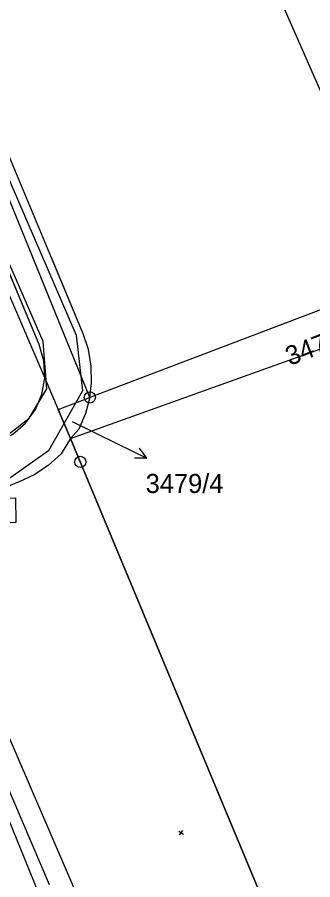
# Model space of a CAD drawing. Extents: x -834064 to -833847, y -1109181 to -1108930.
# Drawn here: x -833930.2 to -833903.8, y -1109136 to -1109058.9 of the extents above; entities that cross this region are included whole.
import ezdxf

# ---------------------------------------------------------------- set-up
doc = ezdxf.new("R2010")
doc.units = 0
for name, color, linetype in [('Hranice parcel', 7, 'Continuous'), ('Parcelní čísla', 7, 'Continuous'), ('Pop  PČ popisy', 7, 'Continuous'), ('Vrstva 49', 7, 'Continuous'), ('Vrstva 51', 7, 'Continuous'), ('Vrstva 53', 7, 'Continuous'), ('Značky bodu BP', 7, 'Continuous')]:
    doc.layers.add(name, color=color, linetype=linetype)

msp = doc.modelspace()

# ---------------------------------------------------------------- linework, layer by layer
at = {"layer": 'Hranice parcel'}
for p, q in [((-833895.8, -1109082.28), (-833914.822, -1109038.767)), ((-833923.74, -1109092.89), (-833941.325, -1109049.812)), ((-833923.74, -1109092.89), (-833928.835, -1109080.41)), ((-833895.8, -1109082.28), (-833923.74, -1109092.89)), ((-833895.8, -1109082.28), (-833923.74, -1109092.89)), ((-833925.47, -1109096.55), (-833894.43, -1109085.46)), ((-833925.47, -1109096.55), (-833894.43, -1109085.46)), ((-833927.77, -1109091.16), (-833926.57, -1109093.96)), ((-833927.77, -1109091.16), (-833926.57, -1109093.96)), ((-833926.57, -1109093.96), (-833923.74, -1109092.89)), ((-833926.57, -1109093.96), (-833923.74, -1109092.89)), ((-833925.47, -1109096.55), (-833926.57, -1109093.96)), ((-833925.47, -1109096.55), (-833926.57, -1109093.96))]:
    msp.add_line(p, q, dxfattribs=at)
for points in [[(-833923.74, -1109092.89), (-833923.58, -1109091.6), (-833923.62, -1109090.1), (-833923.87, -1109088.62), (-833924.35, -1109087.2), (-833940.145, -1109049.32)], [(-833944.996, -1109051.342), (-833931.74, -1109081.87), (-833927.77, -1109091.16)], [(-833927.77, -1109091.16), (-833927.85, -1109089.61), (-833928.27, -1109088.17), (-833943.833, -1109050.857)], [(-833932.374, -1109080.41), (-833931.74, -1109081.87), (-833927.77, -1109091.16)], [(-833927.77, -1109091.16), (-833927.85, -1109089.61), (-833928.27, -1109088.17), (-833931.507, -1109080.41)], [(-833923.74, -1109092.89), (-833923.58, -1109091.6), (-833923.62, -1109090.1), (-833923.87, -1109088.62), (-833924.35, -1109087.2), (-833927.181, -1109080.41)], [(-833951.04, -1109104.84), (-833931.81, -1109096.82), (-833930.62, -1109096.17), (-833929.48, -1109095.19), (-833928.61, -1109093.97), (-833928.02, -1109092.59), (-833927.77, -1109091.16)], [(-833951.04, -1109104.84), (-833931.81, -1109096.82), (-833930.62, -1109096.17), (-833929.48, -1109095.19), (-833928.61, -1109093.97), (-833928.02, -1109092.59), (-833927.77, -1109091.16)], [(-833923.74, -1109092.89), (-833924.13, -1109094.33), (-833924.72, -1109095.71), (-833925.47, -1109096.55)], [(-833923.74, -1109092.89), (-833924.13, -1109094.33), (-833924.72, -1109095.71), (-833925.47, -1109096.55)], [(-833925.47, -1109096.55), (-833926.31, -1109097.93), (-833927.42, -1109098.94), (-833928.67, -1109099.77), (-833929.72, -1109100.28), (-833932.81, -1109101.57), (-833932.34, -1109101.88), (-833930.39, -1109101.86), (-833930.36, -1109104.07), (-833939.02, -1109104.16), (-833949.57, -1109108.56)], [(-833925.47, -1109096.55), (-833926.31, -1109097.93), (-833927.42, -1109098.94), (-833928.67, -1109099.77), (-833929.72, -1109100.28), (-833932.81, -1109101.57), (-833932.34, -1109101.88), (-833930.39, -1109101.86), (-833930.36, -1109104.07), (-833939.02, -1109104.16), (-833949.57, -1109108.56)], [(-833905.178, -1109148.501), (-833906.97, -1109140.92), (-833924.59, -1109098.65), (-833925.47, -1109096.55)], [(-833905.178, -1109148.501), (-833906.97, -1109140.92), (-833924.59, -1109098.65), (-833925.47, -1109096.55)]]:
    msp.add_lwpolyline(points, dxfattribs=at)
at = {"layer": 'Pop  PČ popisy'}
for p, q in [((-833925.31, -1109095.03), (-833921.33, -1109096.99)), ((-833925.31, -1109095.03), (-833921.33, -1109096.99)), ((-833921.33, -1109096.99), (-833918.633, -1109098.306)), ((-833921.33, -1109096.99), (-833918.633, -1109098.306)), ((-833918.633, -1109098.306), (-833919.313, -1109097.416)), ((-833918.633, -1109098.306), (-833919.313, -1109097.416)), ((-833918.633, -1109098.306), (-833919.752, -1109098.317)), ((-833918.633, -1109098.306), (-833919.752, -1109098.317))]:
    msp.add_line(p, q, dxfattribs=at)
at = {"layer": 'Vrstva 49'}
for p, q in [((-833915.723, -1109131.959), (-833915.433, -1109131.551)), ((-833915.782, -1109131.61), (-833915.374, -1109131.9))]:
    msp.add_line(p, q, dxfattribs=at)
for points in [[(-833928.364, -1109137.035), (-833940.743, -1109106.659)], [(-833927.334, -1109136.417), (-833939.456, -1109108.148), (-833938.208, -1109106.483)], [(-833938.208, -1109106.483), (-833925.197, -1109136.624), (-833917.678, -1109153.71)]]:
    msp.add_lwpolyline(points, dxfattribs=at)
at = {"layer": 'Vrstva 51'}
for points in [[(-833940.892, -1109049.632), (-833933.81, -1109066.914), (-833924.957, -1109087.341), (-833924.384, -1109092.301), (-833927.433, -1109097.655), (-833931.105, -1109100.236)], [(-833932.56, -1109097.362), (-833929.169, -1109094.739), (-833927.592, -1109092.134), (-833927.925, -1109087.909), (-833936.504, -1109068.244), (-833943.634, -1109050.774)]]:
    msp.add_lwpolyline(points, dxfattribs=at)
at = {"layer": 'Vrstva 53'}
for points in [[(-833944.996, -1109051.342), (-833931.74, -1109081.87), (-833927.77, -1109091.16)], [(-833927.77, -1109091.16), (-833926.57, -1109093.96), (-833925.47, -1109096.55), (-833924.59, -1109098.65), (-833906.97, -1109140.92), (-833905.178, -1109148.501)]]:
    msp.add_lwpolyline(points, dxfattribs=at)
at = {"layer": 'Značky bodu BP'}
for centre, radius in [((-833923.74, -1109092.89), 0.5), ((-833923.74, -1109092.89), 0.0303), ((-833924.59, -1109098.65), 0.5), ((-833924.59, -1109098.65), 0.0303)]:
    msp.add_circle(centre, radius, dxfattribs=at)

# ---------------------------------------------------------------- texts
at = {"layer": 'Parcelní čísla'}
msp.add_text('3479/1', height=1.7, rotation=21, dxfattribs=at).set_placement((-833905.861, -1109090.078))
msp.add_text('3479/4', height=1.7, dxfattribs=at).set_placement((-833918.75, -1109101.423))

doc.saveas('drawing.dxf')
